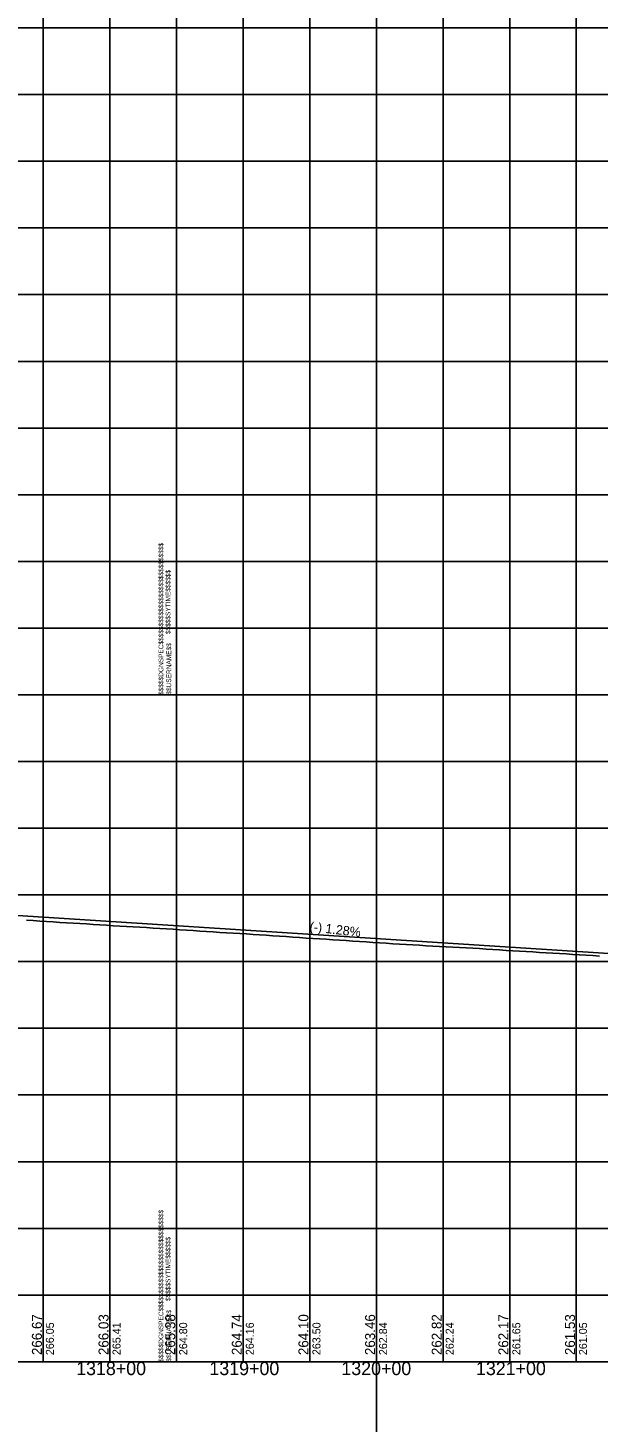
# Model space of a CAD drawing. Extents: x -90830 to 2015517, y -20856 to 836331.
# Drawn here: x 20662 to 21090, y -19432 to -18387 of the extents above; entities that cross this region are included whole.
import ezdxf

# ---------------------------------------------------------------- set-up
doc = ezdxf.new("R2010")
doc.units = 0
for name, color, linetype in [('Level 1', 7, 'Continuous'), ('RD_DDB_GradeTX', 7, 'Continuous'), ('RD_DDB_Profile_Elev', 7, 'Continuous'), ('RD_DDB_Profile_EX', 7, 'Continuous'), ('RD_DDB_Profile_PR', 7, 'Continuous'), ('RD_DDB_StaTX', 7, 'Continuous'), ('RD_DDB_StripGrade', 7, 'Continuous'), ('RD_GPK_Profile_Cell', 7, 'Continuous')]:
    doc.layers.add(name, color=color, linetype=linetype)

msp = doc.modelspace()

# ---------------------------------------------------------------- linework, layer by layer
at = {"layer": 'Level 1'}
for p, q in [((20923.5, -12693.4), (20923.5, -20856.1)), ((20673.5, -17886.5), (20673.5, -18386.5)), ((20723.5, -17886.5), (20723.5, -18386.5)), ((20773.5, -17886.5), (20773.5, -18386.5)), ((20773.5, -17886.5), (20773.5, -18386.5)), ((20773.5, -17886.5), (20773.5, -18386.5)), ((20823.5, -17886.5), (20823.5, -18386.5)), ((20873.5, -17886.5), (20873.5, -18386.5)), ((20923.5, -17886.5), (20923.5, -18386.5)), ((20973.5, -17886.5), (20973.5, -18386.5)), ((21023.5, -17886.5), (21023.5, -18386.5)), ((21073.5, -17886.5), (21073.5, -18386.5)), ((19173.5, -18386.5), (20773.5, -18386.5)), ((19173.5, -18386.5), (20773.5, -18386.5)), ((20673.5, -18386.5), (20673.5, -18886.5)), ((20723.5, -18386.5), (20723.5, -18886.5)), ((20773.5, -18386.5), (20773.5, -18886.5)), ((20773.5, -18386.5), (20773.5, -18886.5)), ((20773.5, -18386.5), (22373.5, -18386.5)), ((20773.5, -18386.5), (20773.5, -18886.5)), ((20773.5, -18386.5), (22373.5, -18386.5)), ((20823.5, -18386.5), (20823.5, -18886.5)), ((20873.5, -18386.5), (20873.5, -18886.5)), ((20923.5, -18386.5), (20923.5, -18886.5)), ((20973.5, -18386.5), (20973.5, -18886.5)), ((21023.5, -18386.5), (21023.5, -18886.5)), ((21073.5, -18386.5), (21073.5, -18886.5)), ((19173.5, -18436.5), (20773.5, -18436.5)), ((20773.5, -18436.5), (22373.5, -18436.5)), ((19173.5, -18486.5), (20773.5, -18486.5)), ((20773.5, -18486.5), (22373.5, -18486.5)), ((19173.5, -18536.5), (20773.5, -18536.5)), ((20773.5, -18536.5), (22373.5, -18536.5)), ((19173.5, -18586.5), (20773.5, -18586.5)), ((20773.5, -18586.5), (22373.5, -18586.5)), ((19173.5, -18636.5), (20773.5, -18636.5)), ((20773.5, -18636.5), (22373.5, -18636.5)), ((19173.5, -18686.5), (20773.5, -18686.5)), ((20773.5, -18686.5), (22373.5, -18686.5)), ((19173.5, -18736.5), (20773.5, -18736.5)), ((20773.5, -18736.5), (22373.5, -18736.5)), ((19173.5, -18786.5), (20773.5, -18786.5)), ((20773.5, -18786.5), (22373.5, -18786.5)), ((19173.5, -18836.5), (20773.5, -18836.5)), ((20773.5, -18836.5), (22373.5, -18836.5)), ((19173.5, -18886.5), (20773.5, -18886.5)), ((19173.5, -18886.5), (20773.5, -18886.5)), ((20673.5, -18886.5), (20673.5, -19386.5)), ((20723.5, -18886.5), (20723.5, -19386.5)), ((20773.5, -18886.5), (20773.5, -19386.5)), ((20773.5, -18886.5), (20773.5, -19386.5)), ((20773.5, -18886.5), (22373.5, -18886.5)), ((20773.5, -18886.5), (22373.5, -18886.5)), ((20773.5, -18886.5), (20773.5, -19386.5)), ((20823.5, -18886.5), (20823.5, -19386.5)), ((20873.5, -18886.5), (20873.5, -19386.5)), ((20923.5, -18886.5), (20923.5, -19386.5)), ((20973.5, -18886.5), (20973.5, -19386.5)), ((21023.5, -18886.5), (21023.5, -19386.5)), ((21073.5, -18886.5), (21073.5, -19386.5)), ((19173.5, -18936.5), (20773.5, -18936.5)), ((20773.5, -18936.5), (22373.5, -18936.5)), ((19173.5, -18986.5), (20773.5, -18986.5)), ((20773.5, -18986.5), (22373.5, -18986.5)), ((19173.5, -19036.5), (20773.5, -19036.5)), ((20773.5, -19036.5), (22373.5, -19036.5)), ((19173.5, -19086.5), (20773.5, -19086.5)), ((20773.5, -19086.5), (22373.5, -19086.5)), ((19173.5, -19136.5), (20773.5, -19136.5)), ((20773.5, -19136.5), (22373.5, -19136.5)), ((19173.5, -19186.5), (20773.5, -19186.5)), ((20773.5, -19186.5), (22373.5, -19186.5)), ((19173.5, -19236.5), (20773.5, -19236.5)), ((20773.5, -19236.5), (22373.5, -19236.5)), ((19173.5, -19286.5), (20773.5, -19286.5)), ((20773.5, -19286.5), (22373.5, -19286.5)), ((19173.5, -19336.5), (20773.5, -19336.5)), ((20773.5, -19336.5), (22373.5, -19336.5)), ((19173.5, -19386.5), (20773.5, -19386.5)), ((20773.5, -19386.5), (22373.5, -19386.5))]:
    msp.add_line(p, q, dxfattribs=at)
at = {"layer": 'RD_DDB_Profile_EX'}
for points in [[(20660.9, -19055.5), (20665.9, -19055.8), (20670.9, -19056.1), (20675.9, -19056.4), (20680.9, -19056.7), (20685.9, -19057.1), (20690.9, -19057.4), (20695.9, -19057.7), (20700.9, -19057.9), (20705.9, -19058.2), (20710.9, -19058.6), (20715.9, -19058.9), (20720.9, -19059.3), (20725.9, -19059.6), (20730.9, -19059.9), (20735.9, -19060.2), (20740.9, -19060.4), (20745.9, -19060.7), (20750.9, -19061), (20755.9, -19061.4), (20760.9, -19061.7), (20765.9, -19062), (20770.9, -19062.3), (20775.9, -19062.7), (20780.9, -19063), (20785.9, -19063.3), (20790.9, -19063.6), (20795.9, -19064), (20800.9, -19064.3), (20805.9, -19064.6), (20810.9, -19064.9), (20815.9, -19065.2), (20820.9, -19065.5), (20825.9, -19065.8), (20830.9, -19066.2), (20835.9, -19066.5), (20840.9, -19066.8), (20845.9, -19067.2), (20850.9, -19067.5), (20855.9, -19067.8), (20860.9, -19068.2), (20865.9, -19068.5), (20870.9, -19068.9), (20875.9, -19069.2), (20880.9, -19069.5), (20885.9, -19069.8), (20890.9, -19070.2), (20895.9, -19070.5), (20900.9, -19070.8), (20905.9, -19071.2), (20910.9, -19071.5), (20915.9, -19071.8), (20920.9, -19072.2), (20925.9, -19072.5), (20930.9, -19072.8), (20935.9, -19073.1), (20940.9, -19073.4), (20945.9, -19073.7), (20950.9, -19074), (20955.9, -19074.3), (20960.9, -19074.6), (20965.9, -19074.9), (20970.9, -19075.2), (20975.9, -19075.4), (20980.9, -19075.7), (20985.9, -19075.9), (20990.9, -19076.2), (20995.9, -19076.5), (21000.9, -19076.8), (21005.9, -19077.1), (21010.9, -19077.4), (21015.9, -19077.7), (21020.9, -19078.1), (21025.9, -19078.4), (21030.9, -19078.7), (21035.9, -19079), (21040.9, -19079.3), (21045.9, -19079.6)], [(21045.9, -19079.6), (21050.9, -19079.9), (21055.9, -19080.2), (21060.9, -19080.5), (21065.9, -19080.8), (21070.9, -19081.1), (21075.9, -19081.4), (21080.9, -19081.7), (21085.9, -19082), (21090.9, -19082.3)]]:
    msp.add_lwpolyline(points, dxfattribs=at)
at = {"layer": 'RD_DDB_Profile_PR'}
msp.add_line((19803.5, -18997.3), (21178.5, -19085.6), dxfattribs=at)
at = {"layer": 'RD_GPK_Profile_Cell'}
msp.add_line((4823.5, -19386.5), (75223.5, -19386.5), dxfattribs=at)

# ---------------------------------------------------------------- texts
at = {"layer": 'Level 1'}
for s, p in [('$$$$$DGNSPEC$$$$$$$$$$$$$$$$$$$$$$$$$$$$', (20763.6, -18886.6)), ('$$$$$SYTIME$$$$$$', (20768.9, -18841)), ('$$USERNAME$$', (20769.5, -18886.4)), ('$$$$$DGNSPEC$$$$$$$$$$$$$$$$$$$$$$$$$$$$', (20763.6, -19386.6)), ('$$$$$SYTIME$$$$$$', (20768.9, -19341)), ('$$USERNAME$$', (20769.5, -19386.4))]:
    msp.add_text(s, height=3.544, rotation=90, dxfattribs=at).set_placement(p)
at = {"layer": 'RD_DDB_GradeTX'}
msp.add_text('(-) 1.28%', height=7, rotation=353.3454, dxfattribs=at).set_placement((20873.1, -19063.6))
at = {"layer": 'RD_DDB_Profile_Elev'}
for s, p in [('266.67', (20672.5, -19381.5)), ('266.03', (20722.5, -19381.5)), ('265.38', (20772.5, -19381.5)), ('264.74', (20822.5, -19381.5)), ('264.10', (20872.5, -19381.5)), ('263.46', (20922.5, -19381.5)), ('262.82', (20972.5, -19381.5)), ('262.17', (21022.5, -19381.5)), ('261.53', (21072.5, -19381.5))]:
    msp.add_text(s, height=7.5, rotation=90, dxfattribs=at).set_placement(p)
at = {"layer": 'RD_DDB_StaTX'}
for s, p in [('1318+00', (20698.2, -19396.5)), ('1319+00', (20798.2, -19396.5)), ('1320+00', (20897.2, -19396.5)), ('1321+00', (20998.2, -19396.5))]:
    msp.add_text(s, height=10, dxfattribs=at).set_placement(p)
at = {"layer": 'RD_DDB_StripGrade'}
for s, p in [('266.05', (20681.5, -19381.5)), ('265.41', (20731.5, -19381.5)), ('264.80', (20781.5, -19381.5)), ('264.16', (20831.5, -19381.5)), ('263.50', (20881.5, -19381.5)), ('262.84', (20931.5, -19381.5)), ('262.24', (20981.5, -19381.5)), ('261.65', (21031.5, -19381.5)), ('261.05', (21081.5, -19381.5))]:
    msp.add_text(s, height=6, rotation=90, dxfattribs=at).set_placement(p)

doc.saveas('drawing.dxf')
